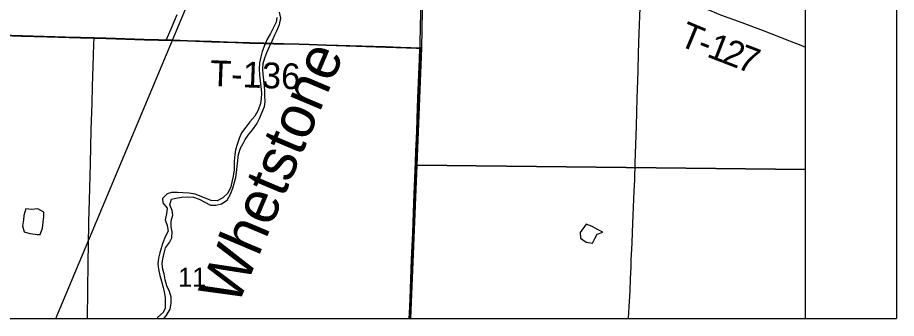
# Model space of a CAD drawing. Extents: x 0 to 34, y 0 to 22.
# Drawn here: x 7.066 to 9, y 14 to 14.663 of the extents above; entities that cross this region are included whole.
import ezdxf

# ---------------------------------------------------------------- set-up
doc = ezdxf.new("R2010")
doc.units = 0
for name, color, linetype in [('Default', 7, 'Continuous'), ('GM_X_City_Street', 7, 'Continuous'), ('GM_X_Corporation', 7, 'Continuous'), ('GM_X_County_Road_Text', 7, 'Continuous'), ('GM_X_Interchange_Ramps', 7, 'Continuous'), ('GM_X_Major_River', 7, 'Continuous'), ('GM_X_Major_River_Text', 7, 'Continuous'), ('GM_X_Section_Text', 7, 'Continuous'), ('GM_X_State_Shield', 7, 'Continuous'), ('GM_X_Unincorporated_Location', 7, 'Continuous'), ('SH_Cut_Line', 7, 'Continuous'), ('SH_Text', 7, 'Continuous')]:
    doc.layers.add(name, color=color, linetype=linetype)

msp = doc.modelspace()

# ---------------------------------------------------------------- linework, layer by layer
at = {"layer": 'Default'}
for points in [[(6.9941, 14.625), (7.0745, 14.6221), (7.1301, 14.6205), (7.2043, 14.6188), (7.2345, 14.6178), (7.2604, 14.6171), (7.3447, 14.6142), (7.376, 14.6134), (7.3929, 14.6132), (7.4087, 14.6127), (7.4399, 14.6117), (7.4928, 14.6101), (7.5457, 14.6081), (7.5769, 14.6071), (7.608, 14.6063), (7.6298, 14.6058), (7.6516, 14.6052), (7.6858, 14.6044), (7.7076, 14.6036), (7.745, 14.6023), (7.8757, 14.5982), (7.9442, 14.5956), (7.9513, 14.5953), (7.9505, 14.5711), (7.9477, 14.5028), (7.9463, 14.4655), (7.9443, 14.4127), (7.9432, 14.3816), (7.9427, 14.3691), (7.9418, 14.3444), (7.9398, 14.2915), (7.938, 14.2543), (7.9357, 14.189), (7.9331, 14.13), (7.9296, 14.043), (7.9281, 14.0108), (7.9275, 14), (8.8, 14), (8.8, 18.8069)], [(2.9377, 14), (7.9275, 14), (7.9281, 14.0108), (7.9296, 14.043), (7.9331, 14.13), (7.9357, 14.189), (7.938, 14.2543), (7.9398, 14.2915), (7.9418, 14.3444), (7.9427, 14.3691), (7.9432, 14.3816), (7.9443, 14.4127), (7.9463, 14.4655), (7.9477, 14.5028), (7.9505, 14.5711), (7.9513, 14.5953), (7.9442, 14.5956), (7.8757, 14.5982), (7.745, 14.6023), (7.7076, 14.6036), (7.6858, 14.6044), (7.6516, 14.6052), (7.6298, 14.6058), (7.608, 14.6063), (7.5769, 14.6071), (7.5457, 14.6081), (7.4928, 14.6101), (7.4399, 14.6117), (7.4087, 14.6127), (7.3929, 14.6132), (7.376, 14.6134), (7.3447, 14.6142), (7.2604, 14.6171), (7.2345, 14.6178), (7.2043, 14.6188), (7.1301, 14.6205), (7.0745, 14.6221), (6.9941, 14.625)]]:
    msp.add_lwpolyline(points, dxfattribs=at)
for points in [[(8.8, 14.3281), (8.8, 15.3246), (7.9679, 15.3374), (7.9551, 14.5952), (7.9448, 14.3373)], [(6.9678, 14), (7.9307, 14), (7.9448, 14.3373), (7.9551, 14.5952), (6.9808, 14.6254)], [(7.9307, 14), (8.8, 14), (8.8, 14.3281), (7.9448, 14.3373)]]:
    msp.add_lwpolyline(points, close=True, dxfattribs=at)
at = {"layer": 'GM_X_City_Street'}
for points in [[(7.9516, 14.5947), (7.952, 14.6079), (7.9537, 14.6731), (7.9564, 14.785), (7.9583, 14.8472), (7.9584, 14.8515)], [(7.9278, 14), (7.9283, 14.0103), (7.9298, 14.0425), (7.9333, 14.1295), (7.936, 14.1885), (7.9383, 14.2537), (7.94, 14.291), (7.9421, 14.3438), (7.943, 14.3686), (7.9434, 14.3811), (7.9445, 14.4121), (7.9465, 14.465), (7.9479, 14.5022), (7.9507, 14.5706), (7.9516, 14.5947)]]:
    msp.add_lwpolyline(points, dxfattribs=at)
at = {"layer": 'GM_X_Corporation'}
msp.add_lwpolyline([(7.1503, 14), (7.403, 14.6041), (7.5398, 14.9308), (7.5529, 14.9621), (7.5767, 15.0193), (7.6567, 15.2102), (7.6827, 15.2726), (7.7324, 15.3914), (7.8087, 15.5745), (7.8264, 15.6162), (7.8444, 15.66), (7.8693, 15.7188), (7.8863, 15.7598), (7.9189, 15.8374), (7.9573, 15.9292), (7.972, 15.9642)], dxfattribs=at)
at = {"layer": 'GM_X_Interchange_Ramps'}
for points in [[(8.4106, 14), (8.4118, 14.026), (8.4139, 14.0601), (8.4151, 14.088), (8.416, 14.1129), (8.4165, 14.1284), (8.4182, 14.1656), (8.4193, 14.1904), (8.4206, 14.2277), (8.423, 14.2805), (8.424, 14.3053), (8.425, 14.3426), (8.4263, 14.3829), (8.4277, 14.4233), (8.4288, 14.4544), (8.4297, 14.4854), (8.4301, 14.5041), (8.4313, 14.5444), (8.4325, 14.5848), (8.434, 14.6283), (8.4357, 14.6842), (8.4369, 14.7246), (8.4372, 14.7495), (8.4371, 14.7506)], [(8.4371, 14.7506), (8.4412, 14.7487), (8.447, 14.7461), (8.4665, 14.7363), (8.5084, 14.7161), (8.5532, 14.6945), (8.5715, 14.6862), (8.5787, 14.683), (8.5922, 14.6773), (8.5987, 14.6745), (8.6132, 14.6689), (8.6599, 14.652), (8.6832, 14.6434), (8.7064, 14.6346), (8.7238, 14.6277), (8.765, 14.6115), (8.7894, 14.6019), (8.8, 14.5979)], [(7.3931, 14.6127), (7.4039, 14.6382), (7.4173, 14.6697)], [(6.9782, 14.6247), (6.9944, 14.6245), (7.0747, 14.6216), (7.1304, 14.62), (7.2045, 14.6182), (7.2347, 14.6173)], [(7.2224, 14.1882), (7.2229, 14.2134), (7.224, 14.2599), (7.2249, 14.2879), (7.2265, 14.3406), (7.2282, 14.4151), (7.23, 14.474), (7.231, 14.5112), (7.2331, 14.5795), (7.2341, 14.6043), (7.2347, 14.6173)], [(7.2347, 14.6173), (7.2606, 14.6166), (7.3449, 14.6136), (7.3762, 14.6128), (7.3931, 14.6127)], [(7.3931, 14.6127), (7.409, 14.6122), (7.4401, 14.6112), (7.493, 14.6096), (7.5459, 14.6076), (7.5771, 14.6065), (7.6082, 14.6057), (7.63, 14.6052), (7.6518, 14.6046), (7.686, 14.6039), (7.7078, 14.6031), (7.7452, 14.6018), (7.876, 14.5977), (7.9444, 14.595), (7.9516, 14.5947)], [(7.2199, 14), (7.2207, 14.0614), (7.2216, 14.1234), (7.2222, 14.1637), (7.2222, 14.1793), (7.2223, 14.1841), (7.2224, 14.1882)]]:
    msp.add_lwpolyline(points, dxfattribs=at)
at = {"layer": 'GM_X_Major_River'}
for points in [[(7.0841, 14.2411), (7.08, 14.227), (7.0793, 14.2175), (7.077, 14.2043), (7.0801, 14.1906), (7.0927, 14.1869), (7.1044, 14.1854), (7.1093, 14.1852)], [(7.1093, 14.1852), (7.1158, 14.185), (7.1211, 14.1987), (7.1222, 14.212), (7.124, 14.2245), (7.124, 14.234), (7.1107, 14.2415), (7.097, 14.2403), (7.0841, 14.2411)], [(8.3171, 14.2073), (8.3042, 14.1891), (8.305, 14.177), (8.3171, 14.1682), (8.3308, 14.1659), (8.3334, 14.1704)], [(8.3334, 14.1704), (8.3365, 14.1758), (8.3415, 14.1853), (8.3537, 14.1899), (8.3419, 14.1959), (8.3301, 14.2028), (8.3171, 14.2073)]]:
    msp.add_lwpolyline(points, dxfattribs=at)
at = {"layer": 'GM_X_Section_Text'}
for points in [[(7.4902, 14.2498), (7.502, 14.2494), (7.5146, 14.2528), (7.5271, 14.2608), (7.5343, 14.2741), (7.5397, 14.2866), (7.5435, 14.3003), (7.5465, 14.3106), (7.5477, 14.3216), (7.5492, 14.3349), (7.5504, 14.3478), (7.5519, 14.3611), (7.5568, 14.3748), (7.5622, 14.385), (7.5667, 14.3945), (7.5755, 14.4063), (7.5827, 14.4158), (7.5922, 14.4283), (7.598, 14.4401), (7.6037, 14.453), (7.609, 14.4667), (7.6109, 14.4773), (7.6098, 14.4903), (7.6098, 14.4998), (7.6094, 14.5119), (7.6079, 14.5248), (7.6064, 14.5381), (7.606, 14.5495), (7.6064, 14.5613), (7.6102, 14.5742), (7.6148, 14.586), (7.6201, 14.5993), (7.6269, 14.6126), (7.6323, 14.6244), (7.6365, 14.6338), (7.6426, 14.6475), (7.6456, 14.6616), (7.6422, 14.6745)], [(7.6365, 14.6631), (7.6353, 14.6528), (7.6292, 14.6407), (7.6224, 14.6274), (7.6148, 14.6137), (7.6091, 14.6012), (7.6045, 14.5883), (7.6014, 14.5761), (7.5984, 14.5632), (7.5976, 14.5499), (7.5984, 14.5366), (7.5995, 14.5233), (7.601, 14.5104), (7.6025, 14.4967), (7.6022, 14.4834), (7.6006, 14.4735), (7.5957, 14.4591), (7.5884, 14.4458), (7.577, 14.4333), (7.5679, 14.4211), (7.5584, 14.409), (7.5538, 14.3964), (7.5492, 14.3831), (7.5454, 14.3714), (7.5443, 14.3611), (7.5427, 14.3467), (7.5427, 14.3372), (7.5424, 14.3277), (7.5404, 14.3136), (7.5385, 14.3041), (7.5351, 14.2901), (7.529, 14.276), (7.5176, 14.2654), (7.505, 14.2593)], [(7.505, 14.2593), (7.4921, 14.2601), (7.4788, 14.265), (7.4663, 14.2703), (7.4564, 14.2734), (7.4434, 14.2757), (7.4297, 14.2764), (7.4176, 14.2772), (7.4046, 14.2772), (7.3951, 14.2745), (7.3852, 14.2639), (7.3856, 14.2544), (7.3951, 14.243), (7.3936, 14.2301), (7.3909, 14.2172), (7.3951, 14.2046), (7.397, 14.1925), (7.3909, 14.1796), (7.3859, 14.1663), (7.3821, 14.1549), (7.3787, 14.1442), (7.3764, 14.1325), (7.3745, 14.1203), (7.376, 14.1082), (7.3787, 14.0949), (7.3829, 14.0819), (7.3866, 14.0683), (7.3885, 14.0584), (7.3904, 14.0458), (7.3908, 14.036), (7.3904, 14.0227), (7.3862, 14.0128), (7.3741, 14.0018), (7.3729, 14)], [(7.3878, 14), (7.3931, 14.006), (7.4018, 14.0204), (7.4041, 14.0337), (7.4041, 14.0466), (7.4003, 14.0591), (7.3946, 14.0721), (7.3905, 14.0854), (7.3882, 14.0979), (7.3859, 14.1078), (7.384, 14.1211), (7.3855, 14.1313), (7.3882, 14.1435), (7.3916, 14.1556), (7.4004, 14.1674), (7.4057, 14.1773), (7.4065, 14.1906), (7.4038, 14.202), (7.4042, 14.2153), (7.4076, 14.2278), (7.4065, 14.2381), (7.4012, 14.2502), (7.405, 14.2624), (7.4145, 14.2647), (7.4271, 14.2669), (7.4408, 14.2681), (7.4533, 14.2673), (7.4655, 14.2627), (7.4777, 14.2559), (7.4902, 14.2498)]]:
    msp.add_lwpolyline(points, dxfattribs=at)
at = {"layer": 'GM_X_Unincorporated_Location'}
msp.add_lwpolyline([(6.9963, 15.6339), (7.9737, 15.6015), (7.9679, 15.3374), (7.9551, 14.5952), (6.9808, 14.6254)], close=True, dxfattribs=at)
at = {"layer": 'SH_Cut_Line'}
for p in [(9, 21), (2, 14)]:
    msp.add_line(p, (9, 14), dxfattribs=at)
at = {"layer": 'SH_Text'}
msp.add_lwpolyline([(2.9377, 14), (8.8, 14), (8.8, 20.8), (2.9842, 20.8), (2.984, 20.7397), (2.9904, 20.3395), (2.9796, 19.7242), (2.9753, 18.7199), (2.9708, 17.6769), (2.9623, 15.7101), (2.9479, 14.7065)], close=True, dxfattribs=at)

# ---------------------------------------------------------------- texts
at = {"layer": 'GM_X_County_Road_Text'}
for s, height, rotation, p in [('T', 0.0568, 337.4553, (8.5181, 14.6028)), ('1', 0.0568, 338.8185, (8.5804, 14.5775)), ('-', 0.0568, 338.6368, (8.5585, 14.5861)), ('2', 0.0568, 338.8757, (8.6131, 14.5648)), ('7', 0.0568, 338.8992, (8.6458, 14.5522)), ('T-136', 0.05682, 357.7568, (7.4887, 14.5121))]:
    msp.add_text(s, height=height, rotation=rotation, dxfattribs=at).set_placement(p)
at = {"layer": 'GM_X_Major_River_Text'}
msp.add_text('11', height=0.04186, rotation=0, dxfattribs=at).set_placement((7.4191, 14.0699))
at = {"layer": 'GM_X_State_Shield'}
msp.add_text('Whetstone', height=0.09471, rotation=67.0764, dxfattribs=at).set_placement((7.5493, 14.0243))

doc.saveas('drawing.dxf')
